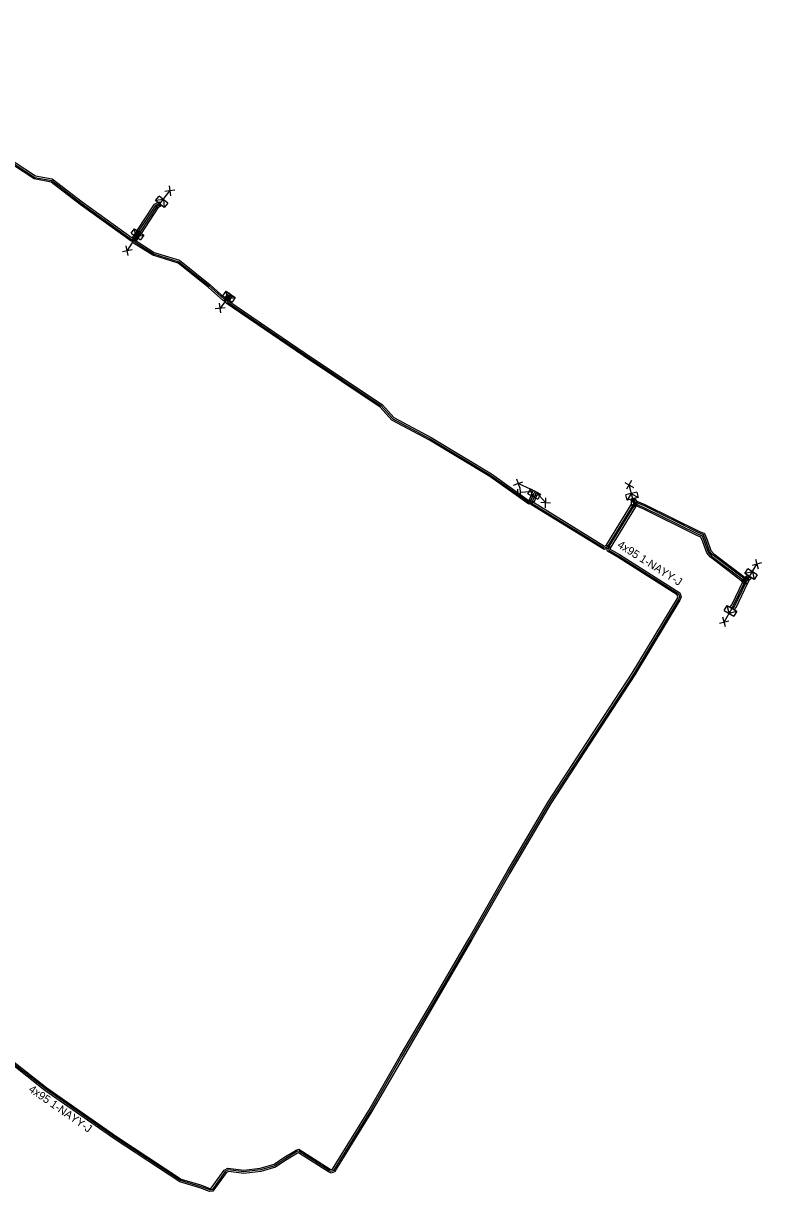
# Model space of a CAD drawing. Extents: x -540466 to -537383, y -1184038 to -1179972.
# Drawn here: x -538918.9 to -538826.7, y -1180988.6 to -1180842.7 of the extents above; entities that cross this region are included whole.
import ezdxf

# ---------------------------------------------------------------- set-up
doc = ezdxf.new("R2010")
doc.units = 0
for name, color, linetype in [('Vrstva 1', 7, 'Continuous'), ('Vrstva 14', 7, 'Continuous'), ('Vrstva 15', 7, 'Continuous'), ('Vrstva 20', 7, 'Continuous'), ('Vrstva 31', 7, 'Continuous'), ('Vrstva 34', 7, 'Continuous'), ('Vrstva 5', 7, 'Continuous'), ('Vrstva 59', 7, 'Continuous'), ('Vrstva 6', 7, 'Continuous'), ('Vrstva 9', 7, 'Continuous')]:
    doc.layers.add(name, color=color, linetype=linetype)

# ---------------------------------------------------------------- blocks, each defined once
blk = doc.blocks.new('NN800')
at = {"layer": 'Vrstva 1'}
for points in [[(-0.44, 0.44), (0.44, -0.44)], [(-0.44, -0.44), (0.44, 0.44)]]:
    blk.add_lwpolyline(points, dxfattribs=at)
blk = doc.blocks.new('NN630')
at = {"layer": 'Vrstva 9'}
for points in [[(0, -0.7), (-0.7, 0)], [(-0.7, -0.7), (-0.7, 0), (0.7, 0), (0.7, -0.7)], [(-0.7, -0.7), (0.7, -0.7)], [(0, -0.7), (0.7, 0)]]:
    blk.add_lwpolyline(points, dxfattribs=at)
blk = doc.blocks.new('NN810')
at = {"layer": 'Vrstva 14'}
for points in [[(0, -0.64), (0, -1.89)], [(0.63, -1.89), (-0.62, -1.89)], [(0.39, -2.2), (-0.4, -2.2)], [(0, -2.52), (-0.12, -2.52)], [(0.14, -2.52), (0, -2.52)]]:
    blk.add_lwpolyline(points, dxfattribs=at)

msp = doc.modelspace()

# ---------------------------------------------------------------- linework, layer by layer
at = {"layer": 'Vrstva 20'}
for points in [[(-538944.48, -1180842.69), (-538935.95, -1180849.02), (-538934.08, -1180850.44), (-538929.9, -1180855.14), (-538928.43, -1180855.37), (-538925.7, -1180856.34), (-538917.42, -1180861.75), (-538915.32, -1180862.13), (-538911.6, -1180864.98), (-538905.35, -1180869.5), (-538905.08, -1180869.5), (-538905.08, -1180869.9), (-538905.47, -1180869.9), (-538911.84, -1180865.3), (-538915.48, -1180862.51), (-538917.58, -1180862.13), (-538925.88, -1180856.7), (-538928.53, -1180855.75), (-538930.1, -1180855.52), (-538934.36, -1180850.74), (-538936.19, -1180849.34), (-538944.72, -1180843.01)], [(-538901.72, -1180865.5), (-538902.12, -1180865.73), (-538904.22, -1180868.92), (-538904.72, -1180868.58), (-538902.54, -1180865.29), (-538902.02, -1180864.98)], [(-538904.22, -1180868.91), (-538904.83, -1180869.86), (-538905.33, -1180869.54), (-538904.72, -1180868.59)], [(-538904.89, -1180869.65), (-538904.83, -1180869.87), (-538902.6, -1180871.3), (-538899.41, -1180872.29), (-538895.6, -1180875.34), (-538893.78, -1180876.96), (-538893.51, -1180876.95), (-538893.49, -1180877.35), (-538893.92, -1180877.36), (-538895.86, -1180875.64), (-538899.61, -1180872.65), (-538902.76, -1180871.66), (-538905.19, -1180870.13), (-538905.27, -1180869.75)], [(-538892.79, -1180876.74), (-538893.27, -1180877.34), (-538893.73, -1180876.96), (-538893.25, -1180876.36)], [(-538893.3, -1180877.11), (-538893.24, -1180877.4), (-538883.7, -1180883.87), (-538874.07, -1180890.33), (-538872.62, -1180891.93), (-538867.99, -1180894.41), (-538860.43, -1180898.96), (-538855.71, -1180902.32), (-538855.5, -1180902.24), (-538855.36, -1180902.62), (-538855.77, -1180902.76), (-538860.65, -1180899.3), (-538868.19, -1180894.75), (-538872.88, -1180892.25), (-538874.33, -1180890.63), (-538883.92, -1180884.21), (-538893.6, -1180877.64), (-538893.7, -1180877.19)], [(-538854.65, -1180901.28), (-538855.15, -1180902.54), (-538855.71, -1180902.32), (-538855.21, -1180901.06)], [(-538842.58, -1180902.07), (-538842.48, -1180902.9), (-538842.88, -1180902.94), (-538842.98, -1180902.11)], [(-538842.62, -1180901.97), (-538842.21, -1180902.52), (-538842.53, -1180902.76), (-538842.94, -1180902.21)], [(-538855.24, -1180902.36), (-538855.18, -1180902.52), (-538846.29, -1180907.98), (-538845.88, -1180907.88), (-538845.8, -1180908.28), (-538846.37, -1180908.4), (-538855.5, -1180902.8), (-538855.62, -1180902.5)], [(-538842.42, -1180903.08), (-538845.58, -1180908.24), (-538846.1, -1180907.92), (-538842.94, -1180902.76)], [(-538842.17, -1180902.86), (-538842.48, -1180903.14), (-538842.75, -1180902.85), (-538842.44, -1180902.57)], [(-538829.09, -1180912.4), (-538833.08, -1180909.38), (-538833.52, -1180908.83), (-538834.03, -1180907.44), (-538834.25, -1180906.88), (-538834.76, -1180906.66), (-538841.49, -1180903.33), (-538842.49, -1180902.92), (-538842.25, -1180902.36), (-538841.25, -1180902.79), (-538834.52, -1180906.12), (-538833.79, -1180906.42), (-538833.47, -1180907.22), (-538833, -1180908.53), (-538832.66, -1180908.94), (-538828.73, -1180911.92)], [(-538830.61, -1180915.59), (-538830.39, -1180915.31), (-538829.02, -1180912.46), (-538828.48, -1180912.72), (-538829.87, -1180915.63), (-538830.15, -1180915.97)], [(-538828.82, -1180912.13), (-538828.66, -1180912.56), (-538829.03, -1180912.69), (-538829.19, -1180912.26)], [(-538828.44, -1180912.27), (-538828.87, -1180912.36), (-538828.95, -1180911.96), (-538828.52, -1180911.87)], [(-538828.21, -1180912.21), (-538828.48, -1180912.73), (-538828.84, -1180912.54), (-538828.57, -1180912.02)], [(-538827.98, -1180912.02), (-538828.28, -1180912.29), (-538828.68, -1180911.85), (-538828.38, -1180911.58)]]:
    msp.add_lwpolyline(points, close=True, dxfattribs=at)
msp.add_lwpolyline([(-538920.31, -1180972.3), (-538916.01, -1180975.67), (-538907.3, -1180981.74), (-538899.22, -1180987.06), (-538896.78, -1180987.8), (-538895.62, -1180988.23), (-538895.46, -1180988.2), (-538893.86, -1180985.97), (-538893.4, -1180985.69), (-538891.4, -1180985.96), (-538889.35, -1180985.7), (-538887.59, -1180985.22), (-538886.38, -1180984.39), (-538884.85, -1180983.46), (-538884.5, -1180983.34), (-538880.6, -1180985.82), (-538880.46, -1180985.89), (-538880.31, -1180985.84), (-538875.75, -1180978.48), (-538871.83, -1180971.66), (-538867.92, -1180965.03), (-538863.22, -1180956.95), (-538858.48, -1180948.64), (-538853.35, -1180939.93), (-538849.16, -1180933.48), (-538842.87, -1180923.87), (-538837.24, -1180914.57), (-538837.14, -1180914.32), (-538837.23, -1180914.07), (-538844.64, -1180909.38), (-538845.95, -1180908.62), (-538846.04, -1180908.11), (-538845.64, -1180908.05), (-538845.59, -1180908.36), (-538844.44, -1180909.04), (-538836.91, -1180913.81), (-538836.72, -1180914.32), (-538836.88, -1180914.75), (-538842.53, -1180924.09), (-538848.82, -1180933.7), (-538853.01, -1180940.15), (-538858.14, -1180948.84), (-538862.88, -1180957.15), (-538867.58, -1180965.23), (-538871.49, -1180971.86), (-538875.41, -1180978.68), (-538880.05, -1180986.18), (-538880.48, -1180986.33), (-538880.8, -1180986.18), (-538884.56, -1180983.78), (-538884.67, -1180983.82), (-538886.16, -1180984.73), (-538887.41, -1180985.58), (-538889.27, -1180986.1), (-538891.4, -1180986.36), (-538893.32, -1180986.11), (-538893.58, -1180986.27), (-538895.24, -1180988.58), (-538895.66, -1180988.63), (-538896.9, -1180988.18), (-538899.4, -1180987.42), (-538907.52, -1180982.08), (-538916.25, -1180975.99), (-538920.77, -1180972.44)], dxfattribs=at)
at = {"layer": 'Vrstva 5'}
for points in [[(-538925.79, -1180856.52), (-538917.5, -1180861.94), (-538915.4, -1180862.32), (-538911.72, -1180865.14), (-538905.41, -1180869.7), (-538905.2, -1180869.7), (-538904.55, -1180868.69), (-538902.4, -1180865.43), (-538902.09, -1180865.25), (-538901.87, -1180865.24), (-538901.99, -1180865.43), (-538902.26, -1180865.58), (-538904.35, -1180868.75), (-538904.47, -1180868.75), (-538904.44, -1180868.89), (-538905.05, -1180869.84), (-538905.01, -1180870), (-538902.68, -1180871.48), (-538899.51, -1180872.47), (-538895.73, -1180875.49), (-538893.85, -1180877.16), (-538893.63, -1180877.15), (-538893.22, -1180876.64), (-538893.02, -1180876.55), (-538893.07, -1180876.77), (-538893.47, -1180877.27), (-538893.42, -1180877.52), (-538883.81, -1180884.04), (-538874.2, -1180890.48), (-538872.75, -1180892.09), (-538868.09, -1180894.58), (-538860.54, -1180899.13), (-538855.74, -1180902.54), (-538855.56, -1180902.48), (-538855.1, -1180901.32), (-538854.93, -1180901.17), (-538854.91, -1180901.39), (-538855.38, -1180902.56), (-538855.34, -1180902.66), (-538846.33, -1180908.19), (-538845.84, -1180908.08)], [(-538845.84, -1180908.08), (-538845.71, -1180908.05), (-538842.6, -1180902.98), (-538842.35, -1180902.76), (-538841.41, -1180903.15), (-538834.68, -1180906.48), (-538834.09, -1180906.73), (-538833.85, -1180907.37), (-538833.35, -1180908.73), (-538832.94, -1180909.23), (-538828.99, -1180912.22), (-538828.86, -1180912.58), (-538830.22, -1180915.42), (-538830.33, -1180915.56), (-538830.38, -1180915.78), (-538830.18, -1180915.69), (-538830.05, -1180915.52), (-538828.64, -1180912.6), (-538828.4, -1180912.13), (-538828.26, -1180912.01), (-538828.18, -1180911.8), (-538828.4, -1180911.86), (-538828.68, -1180912.11), (-538828.78, -1180912.13), (-538832.8, -1180909.09), (-538833.17, -1180908.63), (-538833.66, -1180907.3), (-538833.94, -1180906.58), (-538834.6, -1180906.3), (-538841.32, -1180902.97), (-538842.48, -1180902.49), (-538842.78, -1180902.09), (-538842.7, -1180902.76), (-538845.87, -1180907.93), (-538845.84, -1180908.08)], [(-538845.84, -1180908.08), (-538845.77, -1180908.49), (-538844.54, -1180909.21), (-538837.07, -1180913.94), (-538836.93, -1180914.32), (-538837.06, -1180914.66), (-538842.7, -1180923.98), (-538848.99, -1180933.59), (-538853.18, -1180940.04), (-538858.31, -1180948.74), (-538863.05, -1180957.05), (-538867.75, -1180965.13), (-538871.66, -1180971.76), (-538875.58, -1180978.58), (-538880.18, -1180986.01), (-538880.47, -1180986.11), (-538880.7, -1180986), (-538884.53, -1180983.56), (-538884.76, -1180983.64), (-538886.27, -1180984.56), (-538887.5, -1180985.4), (-538889.31, -1180985.9), (-538891.4, -1180986.16), (-538893.36, -1180985.9), (-538893.72, -1180986.12), (-538895.35, -1180988.39), (-538895.64, -1180988.43), (-538896.84, -1180987.99), (-538899.31, -1180987.24), (-538907.41, -1180981.91), (-538916.13, -1180975.83), (-538920.54, -1180972.37)]]:
    msp.add_lwpolyline(points, dxfattribs=at)
at = {"layer": 'Vrstva 59'}
for points in [[(-538901.87, -1180865.24), (-538900.64, -1180863.61)], [(-538904.47, -1180868.75), (-538905.08, -1180869.7), (-538905.96, -1180871.07)], [(-538893.02, -1180876.55), (-538893.5, -1180877.15), (-538894.35, -1180878.25)], [(-538854.93, -1180901.17), (-538857.09, -1180900.18)], [(-538842.78, -1180902.09), (-538843.24, -1180900.34)], [(-538854.93, -1180901.17), (-538853.66, -1180902.58)], [(-538828.18, -1180911.8), (-538827.27, -1180910.24)], [(-538830.38, -1180915.78), (-538831.35, -1180917.47)]]:
    msp.add_lwpolyline(points, dxfattribs=at)

# ---------------------------------------------------------------- block references
at = {"layer": 'Vrstva 15', "rotation": -86.68897109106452}
msp.add_blockref('NN810', (-538854.93, -1180901.17), dxfattribs=at)
at = {"layer": 'Vrstva 31'}
for p, rotation in [((-538901.87, -1180865.24), 141.34630146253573), ((-538904.47, -1180868.75), -35.22765996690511), ((-538893.02, -1180876.55), -35.10837013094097), ((-538854.93, -1180901.17), -29.054612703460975), ((-538842.78, -1180902.09), -165.10980094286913), ((-538828.18, -1180911.8), 147.28036803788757), ((-538830.38, -1180915.78), -30.549746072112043)]:
    msp.add_blockref('NN630', p, dxfattribs=dict(at, rotation=rotation))
at = {"layer": 'Vrstva 34'}
for p, rotation in [((-538900.64, -1180863.61), -127.08611678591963), ((-538905.96, -1180871.07), 57.3016822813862), ((-538894.35, -1180878.25), 52.057639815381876), ((-538857.09, -1180900.18), -24.57938331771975), ((-538843.24, -1180900.34), -75.15793526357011), ((-538853.66, -1180902.58), 132.03896147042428), ((-538827.27, -1180910.24), -120.12987331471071), ((-538831.35, -1180917.47), 60.15378353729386)]:
    msp.add_blockref('NN800', p, dxfattribs=dict(at, rotation=rotation))

# ---------------------------------------------------------------- texts
at = {"layer": 'Vrstva 6'}
for rotation, p in [(327.658, (-538844.79, -1180908.07)), (325.114, (-538918.37, -1180976.05))]:
    msp.add_text('4x95 1-NAYY-J', height=1, rotation=rotation, dxfattribs=at).set_placement(p)

doc.saveas('drawing.dxf')
